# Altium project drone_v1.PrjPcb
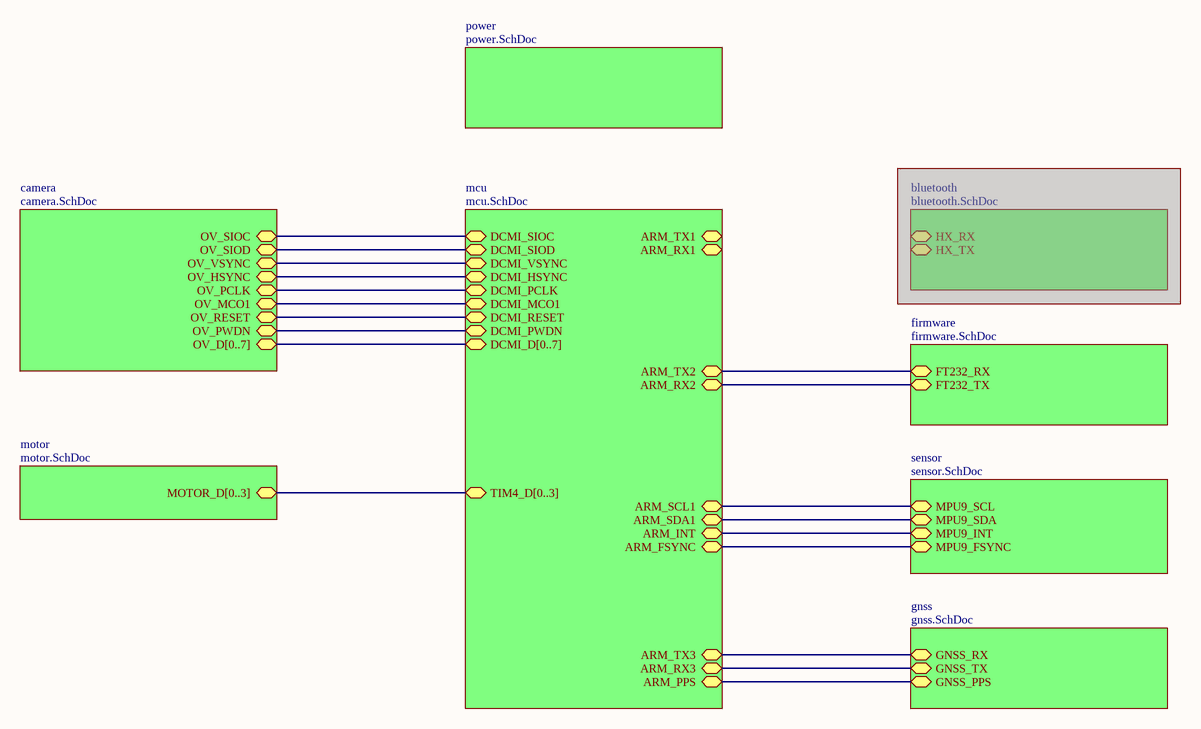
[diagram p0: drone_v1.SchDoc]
9 sheets, 128 parts. Net scope: hierarchical (ports join the sheet entries above them; power ports are global).
Board file: drone_v1.PcbDoc
Sheets:
  drone_v1.SchDoc
    mcu = mcu.SchDoc
    firmware = firmware.SchDoc
    power = power.SchDoc
    sensor = sensor.SchDoc
    gnss = gnss.SchDoc
    camera = camera.SchDoc
    motor = motor.SchDoc

## Sheet drone_v1.SchDoc
size A4

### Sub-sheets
bluetooth = bluetooth.SchDoc (masked out): HX_RX (bidir), HX_TX (bidir)
camera = camera.SchDoc: OV_SIOC (bidir), OV_SIOD (bidir), OV_VSYNC (bidir), OV_HSYNC (bidir), OV_PCLK (bidir), OV_MCO1 (bidir), OV_RESET (bidir), OV_PWDN (bidir), OV_D[0..7] (bidir)
firmware = firmware.SchDoc: FT232_RX (bidir), FT232_TX (bidir)
gnss = gnss.SchDoc: GNSS_RX (bidir), GNSS_TX (bidir), GNSS_PPS (bidir)
mcu = mcu.SchDoc: ARM_TX1 (bidir), ARM_RX1 (bidir), ARM_TX2 (bidir), ARM_RX2 (bidir), ARM_SCL1 (bidir), ARM_SDA1 (bidir), ARM_TX3 (bidir), ARM_RX3 (bidir), DCMI_SIOC (bidir), DCMI_SIOD (bidir), DCMI_VSYNC (bidir), DCMI_HSYNC (bidir), DCMI_PCLK (bidir), DCMI_MCO1 (bidir), DCMI_RESET (bidir), DCMI_PWDN (bidir), DCMI_D[0..7] (bidir), ARM_PPS (bidir), ARM_INT (bidir), ARM_FSYNC (bidir), TIM4_D[0..3] (bidir)
motor = motor.SchDoc: MOTOR_D[0..3] (bidir)
power = power.SchDoc: no entries
sensor = sensor.SchDoc: MPU9_SCL (bidir), MPU9_SDA (bidir), MPU9_INT (bidir), MPU9_FSYNC (bidir)

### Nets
OV_HSYNC: sheet mcu/DCMI_HSYNC, sheet camera/OV_HSYNC
OV_MCO1: sheet mcu/DCMI_MCO1, sheet camera/OV_MCO1
OV_PCLK: sheet mcu/DCMI_PCLK, sheet camera/OV_PCLK
OV_PWDN: sheet mcu/DCMI_PWDN, sheet camera/OV_PWDN
OV_RESET: sheet mcu/DCMI_RESET, sheet camera/OV_RESET
OV_SIOC: sheet mcu/DCMI_SIOC, sheet camera/OV_SIOC
OV_SIOD: sheet mcu/DCMI_SIOD, sheet camera/OV_SIOD
OV_VSYNC: sheet mcu/DCMI_VSYNC, sheet camera/OV_VSYNC
NetR42_2: sheet mcu/ARM_SCL1, sheet sensor/MPU9_SCL
NetR43_2: sheet mcu/ARM_SDA1, sheet sensor/MPU9_SDA
NetR52_1: sheet mcu/ARM_PPS, sheet gnss/GNSS_PPS
NetU1_25: sheet mcu/ARM_TX2, sheet firmware/FT232_RX
NetU1_26: sheet mcu/ARM_RX2, sheet firmware/FT232_TX
NetU1_51: sheet mcu/ARM_FSYNC, sheet sensor/MPU9_FSYNC
NetU1_52: sheet mcu/ARM_INT, sheet sensor/MPU9_INT
NetU1_55: sheet mcu/ARM_TX3, sheet gnss/GNSS_RX
NetU1_56: sheet mcu/ARM_RX3, sheet gnss/GNSS_TX

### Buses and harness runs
bus sheet camera/OV_D[0..7] = sheet mcu/DCMI_D[0..7]
bus sheet mcu/TIM4_D[0..3] = sheet motor/MOTOR_D[0..3]

## Sheet mcu.SchDoc
size A3
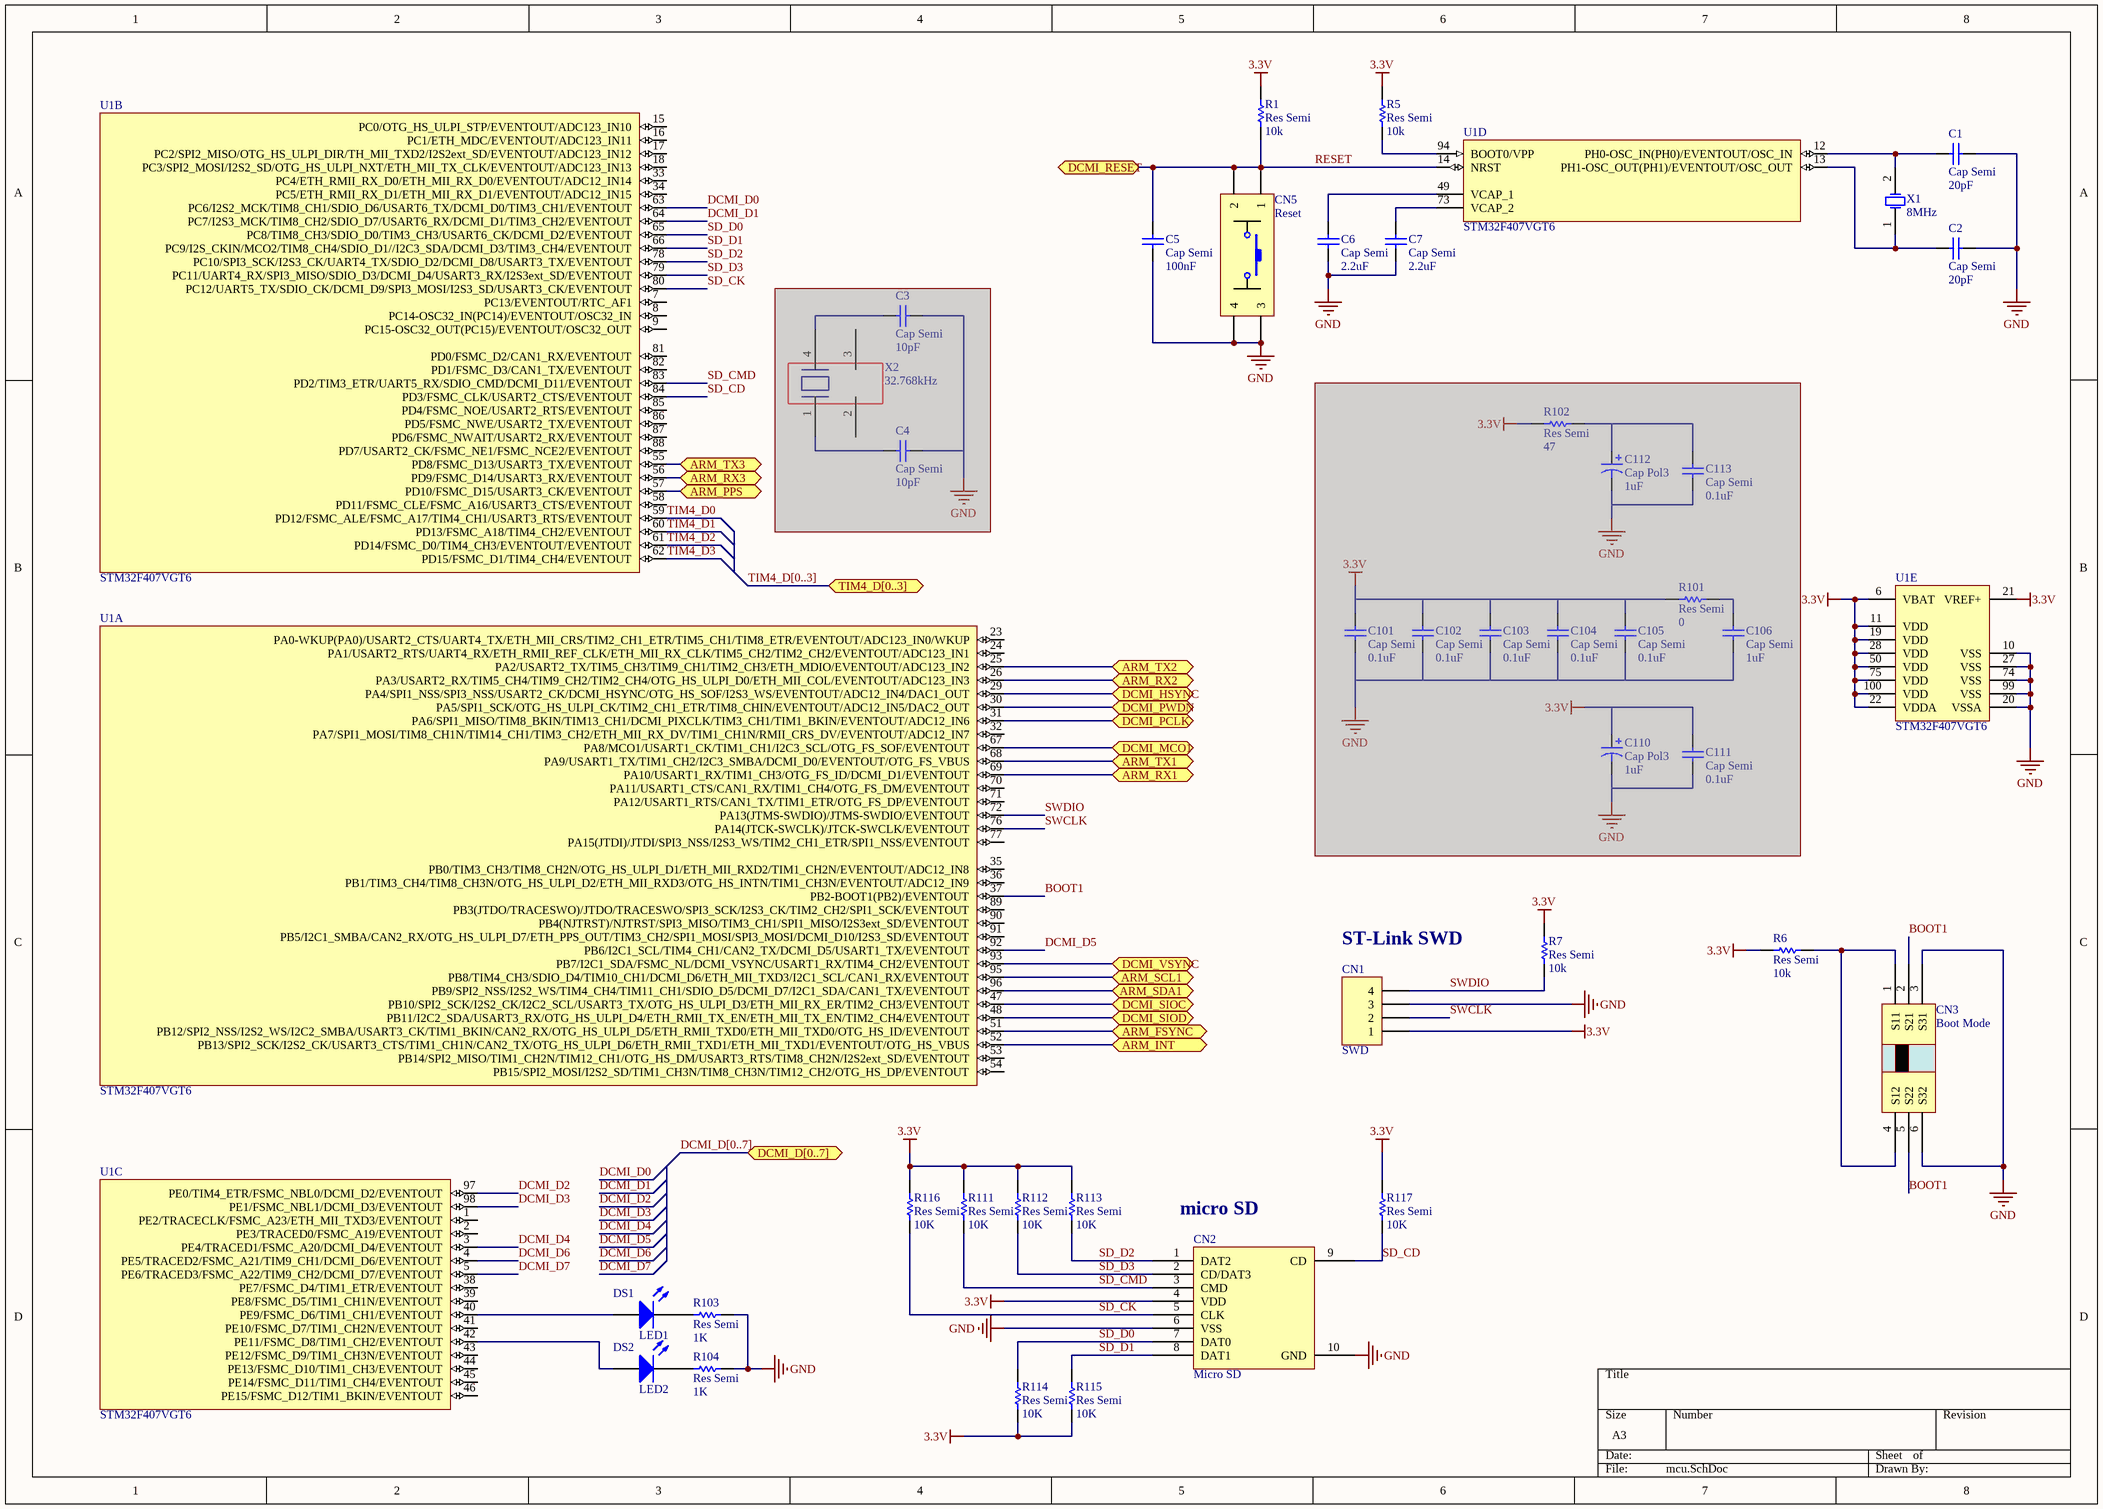
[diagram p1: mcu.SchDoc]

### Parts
C1  Cap Semi  value 20pF  [C1608-0603]
C2  Cap Semi  value 20pF  [C1608-0603]
C3  Cap Semi  value 10pF  [C1608-0603]  (masked out: inside a compile mask, not in the netlist)
C4  Cap Semi  value 10pF  [C1608-0603]  (masked out: inside a compile mask, not in the netlist)
C5  Cap Semi  value 100nF  [C1608-0603]
C6  Cap Semi  value 2.2uF  [C1608-0603]
C7  Cap Semi  value 2.2uF  [C1608-0603]
C101  Cap Semi  value 0.1uF  [C1608-0603]  (masked out: inside a compile mask, not in the netlist)
C102  Cap Semi  value 0.1uF  [C1608-0603]  (masked out: inside a compile mask, not in the netlist)
C103  Cap Semi  value 0.1uF  [C1608-0603]  (masked out: inside a compile mask, not in the netlist)
C104  Cap Semi  value 0.1uF  [C1608-0603]  (masked out: inside a compile mask, not in the netlist)
C105  Cap Semi  value 0.1uF  [C1608-0603]  (masked out: inside a compile mask, not in the netlist)
C106  Cap Semi  value 1uF  [C1608-0603]  (masked out: inside a compile mask, not in the netlist)
C110  Cap Pol3  value 1uF  [CC3216-1206]  (masked out: inside a compile mask, not in the netlist)
C111  Cap Semi  value 0.1uF  [C1608-0603]  (masked out: inside a compile mask, not in the netlist)
C112  Cap Pol3  value 1uF  [CC3216-1206]  (masked out: inside a compile mask, not in the netlist)
C113  Cap Semi  value 0.1uF  [C1608-0603]  (masked out: inside a compile mask, not in the netlist)
CN1  SWD  [HDR1X4H]
CN2  Micro SD  [MICRO_SD_PUSH]
CN3  Boot Mode  [SWITCH_6]
CN5  Reset  [Switch6X6]
DS1  LED1  [LED0603_AB]
DS2  LED2  [LED0603_AB]
R1  Res Semi  value 10k  [R1608-0603]
R5  Res Semi  value 10k  [R1608-0603]
R6  Res Semi  value 10k  [R1608-0603]
R7  Res Semi  value 10k  [R1608-0603]
R101  Res Semi  value 0  [R1608-0603]  (masked out: inside a compile mask, not in the netlist)
R102  Res Semi  value 47  [R1608-0603]  (masked out: inside a compile mask, not in the netlist)
R103  Res Semi  value 1K  [R1608-0603]
R104  Res Semi  value 1K  [R1608-0603]
R111  Res Semi  value 10K  [R1608-0603]
R112  Res Semi  value 10K  [R1608-0603]
R113  Res Semi  value 10K  [R1608-0603]
R114  Res Semi  value 10K  [R1608-0603]
R115  Res Semi  value 10K  [R1608-0603]
R116  Res Semi  value 10K  [R1608-0603]
R117  Res Semi  value 10K  [R1608-0603]
U1  STM32F407VGT6  [LQFP100_V]  (parts A,B,C,D,E of 5)
X1  8MHz  [XTAL-0.2]
X2  32.768kHz  [OSC_MC306]  (masked out: inside a compile mask, not in the netlist)

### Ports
ARM_FSYNC (bidir), ARM_INT (bidir), ARM_PPS (bidir), ARM_RX1 (bidir), ARM_RX2 (bidir), ARM_RX3 (bidir), ARM_SCL1 (bidir), ARM_SDA1 (bidir), ARM_TX1 (bidir), ARM_TX2 (bidir), ARM_TX3 (bidir), DCMI_D[0..7] (bidir), DCMI_HSYNC (bidir), DCMI_MCO1 (bidir), DCMI_PCLK (bidir), DCMI_PWDN (bidir), DCMI_RESET (bidir), DCMI_SIOC (bidir), DCMI_SIOD (bidir), DCMI_VSYNC (bidir), TIM4_D[0..3] (bidir)

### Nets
3.3V: CN1.1 CN2.4(VDD) R1.1 R5.1 R6.1 R7.1 R111.1 R112.1 R113.1 R114.2 R115.2 R116.1 R117.1 U1.6(VBAT) U1.11(VDD) U1.19(VDD) U1.21(VREF+) U1.22(VDDA) U1.28(VDD) U1.50(VDD) U1.75(VDD) U1.100(VDD)
GND: C1.1 C2.1 C5.2 C6.1 C7.1 CN1.3 CN2.6(VSS) CN2.10(GND) CN3.3(S31) CN3.6(S32) CN5.3 CN5.4 R103.2 R104.2 U1.10(VSS) U1.20(VSSA) U1.27(VSS) U1.74(VSS) U1.99(VSS)
BOOT1: CN3.2(S21) CN3.5(S22) U1.37(PB2-BOOT1(PB2)/EVENTOUT)
DCMI_D0: U1.63(PC6/I2S2_MCK/TIM8_CH1/SDIO_D6/USART6_TX/DCMI_D0/TIM3_CH1/EVENTOUT)
DCMI_D1: U1.64(PC7/I2S3_MCK/TIM8_CH2/SDIO_D7/USART6_RX/DCMI_D1/TIM3_CH2/EVENTOUT)
DCMI_D2: U1.97(PE0/TIM4_ETR/FSMC_NBL0/DCMI_D2/EVENTOUT)
DCMI_D3: U1.98(PE1/FSMC_NBL1/DCMI_D3/EVENTOUT)
DCMI_D4: U1.3(PE4/TRACED1/FSMC_A20/DCMI_D4/EVENTOUT)
DCMI_D5: U1.92(PB6/I2C1_SCL/TIM4_CH1/CAN2_TX/DCMI_D5/USART1_TX/EVENTOUT)
DCMI_D6: U1.4(PE5/TRACED2/FSMC_A21/TIM9_CH1/DCMI_D6/EVENTOUT)
DCMI_D7: U1.5(PE6/TRACED3/FSMC_A22/TIM9_CH2/DCMI_D7/EVENTOUT)
OV_HSYNC: U1.29(PA4/SPI1_NSS/SPI3_NSS/USART2_CK/DCMI_HSYNC/OTG_HS_SOF/I2S3_WS/EVENTOUT/ADC12_IN4/DAC1_OUT) ; port DCMI_HSYNC
OV_MCO1: U1.67(PA8/MCO1/USART1_CK/TIM1_CH1/I2C3_SCL/OTG_FS_SOF/EVENTOUT) ; port DCMI_MCO1
OV_PCLK: U1.31(PA6/SPI1_MISO/TIM8_BKIN/TIM13_CH1/DCMI_PIXCLK/TIM3_CH1/TIM1_BKIN/EVENTOUT/ADC12_IN6) ; port DCMI_PCLK
OV_PWDN: U1.30(PA5/SPI1_SCK/OTG_HS_ULPI_CK/TIM2_CH1_ETR/TIM8_CHIN/EVENTOUT/ADC12_IN5/DAC2_OUT) ; port DCMI_PWDN
OV_SIOC: U1.47(PB10/SPI2_SCK/I2S2_CK/I2C2_SCL/USART3_TX/OTG_HS_ULPI_D3/ETH_MII_RX_ER/TIM2_CH3/EVENTOUT) ; port DCMI_SIOC
OV_SIOD: U1.48(PB11/I2C2_SDA/USART3_RX/OTG_HS_ULPI_D4/ETH_RMII_TX_EN/ETH_MII_TX_EN/TIM2_CH4/EVENTOUT) ; port DCMI_SIOD
OV_VSYNC: U1.93(PB7/I2C1_SDA/FSMC_NL/DCMI_VSYNC/USART1_RX/TIM4_CH2/EVENTOUT) ; port DCMI_VSYNC
RESET: C5.1 CN5.1 CN5.2 R1.2 U1.14(NRST) ; port DCMI_RESET  [project net OV_RESET]
SD_CD: CN2.9(CD) R117.2 U1.84(PD3/FSMC_CLK/USART2_CTS/EVENTOUT)
SD_CK: CN2.5(CLK) R116.2 U1.80(PC12/UART5_TX/SDIO_CK/DCMI_D9/SPI3_MOSI/I2S3_SD/USART3_CK/EVENTOUT)
SD_CMD: CN2.3(CMD) R111.2 U1.83(PD2/TIM3_ETR/UART5_RX/SDIO_CMD/DCMI_D11/EVENTOUT)
SD_D0: CN2.7(DAT0) R114.1 U1.65(PC8/TIM8_CH3/SDIO_D0/TIM3_CH3/USART6_CK/DCMI_D2/EVENTOUT)
SD_D1: CN2.8(DAT1) R115.1 U1.66(PC9/I2S_CKIN/MCO2/TIM8_CH4/SDIO_D1//I2C3_SDA/DCMI_D3/TIM3_CH4/EVENTOUT)
SD_D2: CN2.1(DAT2) R113.2 U1.78(PC10/SPI3_SCK/I2S3_CK/UART4_TX/SDIO_D2/DCMI_D8/USART3_TX/EVENTOUT)
SD_D3: CN2.2(CD/DAT3) R112.2 U1.79(PC11/UART4_RX/SPI3_MISO/SDIO_D3/DCMI_D4/USART3_RX/I2S3ext_SD/EVENTOUT)
SWCLK: CN1.2 U1.76(PA14(JTCK-SWCLK)/JTCK-SWCLK/EVENTOUT)
SWDIO: CN1.4 R7.2 U1.72(PA13(JTMS-SWDIO)/JTMS-SWDIO/EVENTOUT)
TIM4_D0: U1.59(PD12/FSMC_ALE/FSMC_A17/TIM4_CH1/USART3_RTS/EVENTOUT)  [project net MOTOR_D0]
TIM4_D1: U1.60(PD13/FSMC_A18/TIM4_CH2/EVENTOUT)  [project net MOTOR_D1]
TIM4_D2: U1.61(PD14/FSMC_D0/TIM4_CH3/EVENTOUT/EVENTOUT)  [project net MOTOR_D2]
TIM4_D3: U1.62(PD15/FSMC_D1/TIM4_CH4/EVENTOUT)  [project net MOTOR_D3]
NetC1_2: C1.2 U1.12(PH0-OSC_IN(PH0)/EVENTOUT/OSC_IN) X1.2(OSC2)
NetC2_2: C2.2 U1.13(PH1-OSC_OUT(PH1)/EVENTOUT/OSC_OUT) X1.1(OSC1)
NetC6_2: C6.2 U1.49(VCAP_1)
NetC7_2: C7.2 U1.73(VCAP_2)
NetCN3_1: CN3.1(S11) CN3.4(S12) R6.2
NetDS1_1: DS1.1(A) U1.40(PE9/FSMC_D6/TIM1_CH1/EVENTOUT)
NetDS1_2: DS1.2(K) R103.1
NetDS2_1: DS2.1(A) U1.42(PE11/FSMC_D8/TIM1_CH2/EVENTOUT)
NetDS2_2: DS2.2(K) R104.1
NetR5_2: R5.2 U1.94(BOOT0/VPP)
NetR42_2: U1.95(PB8/TIM4_CH3/SDIO_D4/TIM10_CH1/DCMI_D6/ETH_MII_TXD3/I2C1_SCL/CAN1_RX/EVENTOUT) ; port ARM_SCL1
NetR43_2: U1.96(PB9/SPI2_NSS/I2S2_WS/TIM4_CH4/TIM11_CH1/SDIO_D5/DCMI_D7/I2C1_SDA/CAN1_TX/EVENTOUT) ; port ARM_SDA1
NetR52_1: U1.57(PD10/FSMC_D15/USART3_CK/EVENTOUT) ; port ARM_PPS
NetU1_25: U1.25(PA2/USART2_TX/TIM5_CH3/TIM9_CH1/TIM2_CH3/ETH_MDIO/EVENTOUT/ADC123_IN2) ; port ARM_TX2
NetU1_26: U1.26(PA3/USART2_RX/TIM5_CH4/TIM9_CH2/TIM2_CH4/OTG_HS_ULPI_D0/ETH_MII_COL/EVENTOUT/ADC123_IN3) ; port ARM_RX2
NetU1_51: U1.51(PB12/SPI2_NSS/I2S2_WS/I2C2_SMBA/USART3_CK/TIM1_BKIN/CAN2_RX/OTG_HS_ULPI_D5/ETH_RMII_TXD0/ETH_MII_TXD0/OTG_HS_ID/EVENTOUT) ; port ARM_FSYNC
NetU1_52: U1.52(PB13/SPI2_SCK/I2S2_CK/USART3_CTS/TIM1_CH1N/CAN2_TX/OTG_HS_ULPI_D6/ETH_RMII_TXD1/ETH_MII_TXD1/EVENTOUT/OTG_HS_VBUS) ; port ARM_INT
NetU1_55: U1.55(PD8/FSMC_D13/USART3_TX/EVENTOUT) ; port ARM_TX3
NetU1_56: U1.56(PD9/FSMC_D14/USART3_RX/EVENTOUT) ; port ARM_RX3
NetU1_68: U1.68(PA9/USART1_TX/TIM1_CH2/I2C3_SMBA/DCMI_D0/EVENTOUT/OTG_FS_VBUS) ; port ARM_TX1
NetU1_69: U1.69(PA10/USART1_RX/TIM1_CH3/OTG_FS_ID/DCMI_D1/EVENTOUT) ; port ARM_RX1

Not connected (* = marked no-connect by the designer): U1 1(PE2/TRACECLK/FSMC_A23/ETH_MII_TXD3/EVENTOUT) 2(PE3/TRACED0/FSMC_A19/EVENTOUT) 7(PC13/EVENTOUT/RTC_AF1) 8(PC14-OSC32_IN(PC14)/EVENTOUT/OSC32_IN) 9(PC15-OSC32_OUT(PC15)/EVENTOUT/OSC32_OUT) 15(PC0/OTG_HS_ULPI_STP/EVENTOUT/ADC123_IN10) 16(PC1/ETH_MDC/EVENTOUT/ADC123_IN11) 17(PC2/SPI2_MISO/OTG_HS_ULPI_DIR/TH_MII_TXD2/I2S2ext_SD/EVENTOUT/ADC123_IN12) 18(PC3/SPI2_MOSI/I2S2_SD/OTG_HS_ULPI_NXT/ETH_MII_TX_CLK/EVENTOUT/ADC123_IN13) 23(PA0-WKUP(PA0)/USART2_CTS/UART4_TX/ETH_MII_CRS/TIM2_CH1_ETR/TIM5_CH1/TIM8_ETR/EVENTOUT/ADC123_IN0/WKUP) 24(PA1/USART2_RTS/UART4_RX/ETH_RMII_REF_CLK/ETH_MII_RX_CLK/TIM5_CH2/TIM2_CH2/EVENTOUT/ADC123_IN1) 32(PA7/SPI1_MOSI/TIM8_CH1N/TIM14_CH1/TIM3_CH2/ETH_MII_RX_DV/TIM1_CH1N/RMII_CRS_DV/EVENTOUT/ADC12_IN7) 33(PC4/ETH_RMII_RX_D0/ETH_MII_RX_D0/EVENTOUT/ADC12_IN14) 34(PC5/ETH_RMII_RX_D1/ETH_MII_RX_D1/EVENTOUT/ADC12_IN15) 35(PB0/TIM3_CH3/TIM8_CH2N/OTG_HS_ULPI_D1/ETH_MII_RXD2/TIM1_CH2N/EVENTOUT/ADC12_IN8) 36(PB1/TIM3_CH4/TIM8_CH3N/OTG_HS_ULPI_D2/ETH_MII_RXD3/OTG_HS_INTN/TIM1_CH3N/EVENTOUT/ADC12_IN9) 38(PE7/FSMC_D4/TIM1_ETR/EVENTOUT) 39(PE8/FSMC_D5/TIM1_CH1N/EVENTOUT) 41(PE10/FSMC_D7/TIM1_CH2N/EVENTOUT) 43(PE12/FSMC_D9/TIM1_CH3N/EVENTOUT) 44(PE13/FSMC_D10/TIM1_CH3/EVENTOUT) 45(PE14/FSMC_D11/TIM1_CH4/EVENTOUT) 46(PE15/FSMC_D12/TIM1_BKIN/EVENTOUT) 53(PB14/SPI2_MISO/TIM1_CH2N/TIM12_CH1/OTG_HS_DM/USART3_RTS/TIM8_CH2N/I2S2ext_SD/EVENTOUT) 54(PB15/SPI2_MOSI/I2S2_SD/TIM1_CH3N/TIM8_CH3N/TIM12_CH2/OTG_HS_DP/EVENTOUT) 58(PD11/FSMC_CLE/FSMC_A16/USART3_CTS/EVENTOUT) 70(PA11/USART1_CTS/CAN1_RX/TIM1_CH4/OTG_FS_DM/EVENTOUT) 71(PA12/USART1_RTS/CAN1_TX/TIM1_ETR/OTG_FS_DP/EVENTOUT) 77(PA15(JTDI)/JTDI/SPI3_NSS/I2S3_WS/TIM2_CH1_ETR/SPI1_NSS/EVENTOUT) 81(PD0/FSMC_D2/CAN1_RX/EVENTOUT) 82(PD1/FSMC_D3/CAN1_TX/EVENTOUT) 85(PD4/FSMC_NOE/USART2_RTS/EVENTOUT) 86(PD5/FSMC_NWE/USART2_TX/EVENTOUT) 87(PD6/FSMC_NWAIT/USART2_RX/EVENTOUT) 88(PD7/USART2_CK/FSMC_NE1/FSMC_NCE2/EVENTOUT) 89(PB3(JTDO/TRACESWO)/JTDO/TRACESWO/SPI3_SCK/I2S3_CK/TIM2_CH2/SPI1_SCK/EVENTOUT) 90(PB4(NJTRST)/NJTRST/SPI3_MISO/TIM3_CH1/SPI1_MISO/I2S3ext_SD/EVENTOUT) 91(PB5/I2C1_SMBA/CAN2_RX/OTG_HS_ULPI_D7/ETH_PPS_OUT/TIM3_CH2/SPI1_MOSI/SPI3_MOSI/DCMI_D10/I2S3_SD/EVENTOUT)

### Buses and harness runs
bus DCMI_D[0..7] = port DCMI_D[0..7]
bus TIM4_D[0..3] = port TIM4_D[0..3]

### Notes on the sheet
- (near CN1) ST-Link SWD
- (near CN2) micro SD

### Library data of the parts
C1-C7 C101-C106 C111 C113 = Cap Semi: Capacitor (Semiconductor SIM Model)
C110 C112 = Cap Pol3: Polarized Capacitor (Surface Mount)
CN1 = Header 4H: Header, 4-Pin, Right Angle
CN2 = MICRO_SD_PUSH
CN3 = SWITCH_6
CN5 = Switch6X6: Switch
DS1 DS2 = LED3: Typical BLUE SiC LED
R1 R5-R7 R101-R104 R111-R117 = Res Semi: Semiconductor Resistor
X1 = XTAL: Crystal Oscillator
X2 = OSC_MC306

## Sheet firmware.SchDoc
size A4
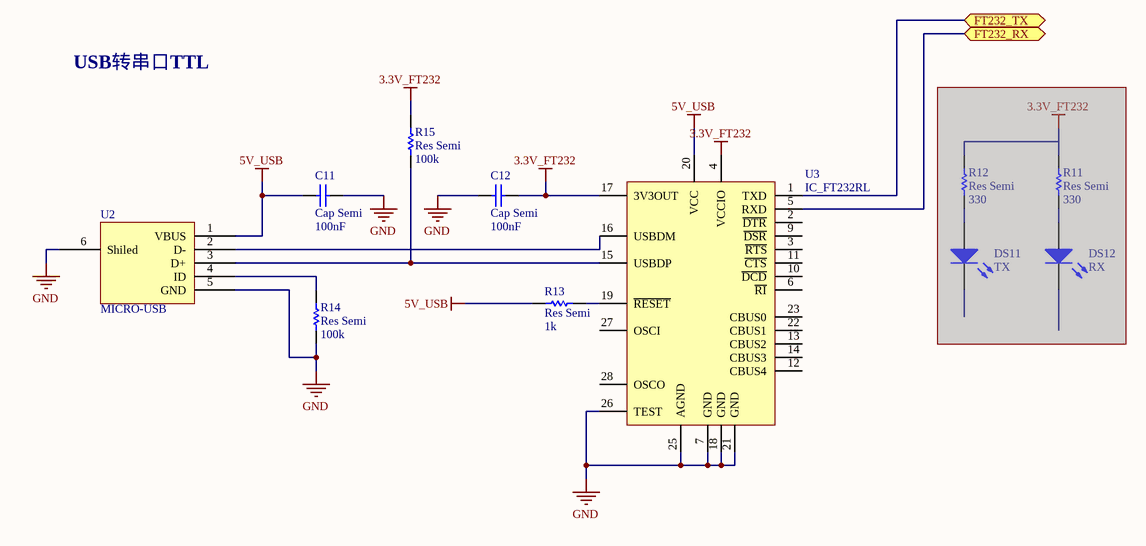
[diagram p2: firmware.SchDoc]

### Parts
C11  Cap Semi  value 100nF  [C1608-0603]
C12  Cap Semi  value 100nF  [C1608-0603]
DS11  TX  [LED0603_AB]  (masked out: inside a compile mask, not in the netlist)
DS12  RX  [LED0603_AB]  (masked out: inside a compile mask, not in the netlist)
R11  Res Semi  value 330  [R1608-0603]  (masked out: inside a compile mask, not in the netlist)
R12  Res Semi  value 330  [R1608-0603]  (masked out: inside a compile mask, not in the netlist)
R13  Res Semi  value 1k  [R1608-0603]
R14  Res Semi  value 100k  [R1608-0603]
R15  Res Semi  value 100k  [R1608-0603]
U2  MICRO-USB  [MICRO-USB]
U3  IC_FT232RL  [SSOP-28]

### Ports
FT232_RX (bidir), FT232_TX (bidir)

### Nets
3.3V_FT232: C12.2 R15.1 U3.4(VCCIO) U3.17(3V3OUT)
5V_USB: C11.1 R13.1 U2.1(VBUS) U3.20(VCC)
GND: C11.2 C12.1 R14.2 U2.5(GND) U2.6(Shiled) U3.7(GND) U3.18(GND) U3.21(GND) U3.25(AGND) U3.26(TEST)
NetR13_2: R13.2 U3.19(~{RESET})
NetR14_1: R14.1 U2.4(ID)
NetR15_2: R15.2 U2.3(D+) U3.15(USBDP)
NetU1_25: U3.5(RXD) ; port FT232_RX
NetU1_26: U3.1(TXD) ; port FT232_TX
NetU2_2: U2.2(D-) U3.16(USBDM)

Not connected (* = marked no-connect by the designer): U3 2(~{DTR}) 3(~{RTS}) 6(~{RI}) 8(NC) 9(~{DSR}) 10(~{DCD}) 11(~{CTS}) 12(CBUS4) 13(CBUS2) 14(CBUS3) 22(CBUS1) 23(CBUS0) 24(NC) 27(OSCI) 28(OSCO)

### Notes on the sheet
- USB转串口TTL

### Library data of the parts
C11 C12 = Cap Semi: Capacitor (Semiconductor SIM Model)
DS11 DS12 = LED3: Typical BLUE SiC LED
R11-R15 = Res Semi: Semiconductor Resistor
U3 = IC_FT232RL: FT232R USB UART

## Sheet power.SchDoc
size A4
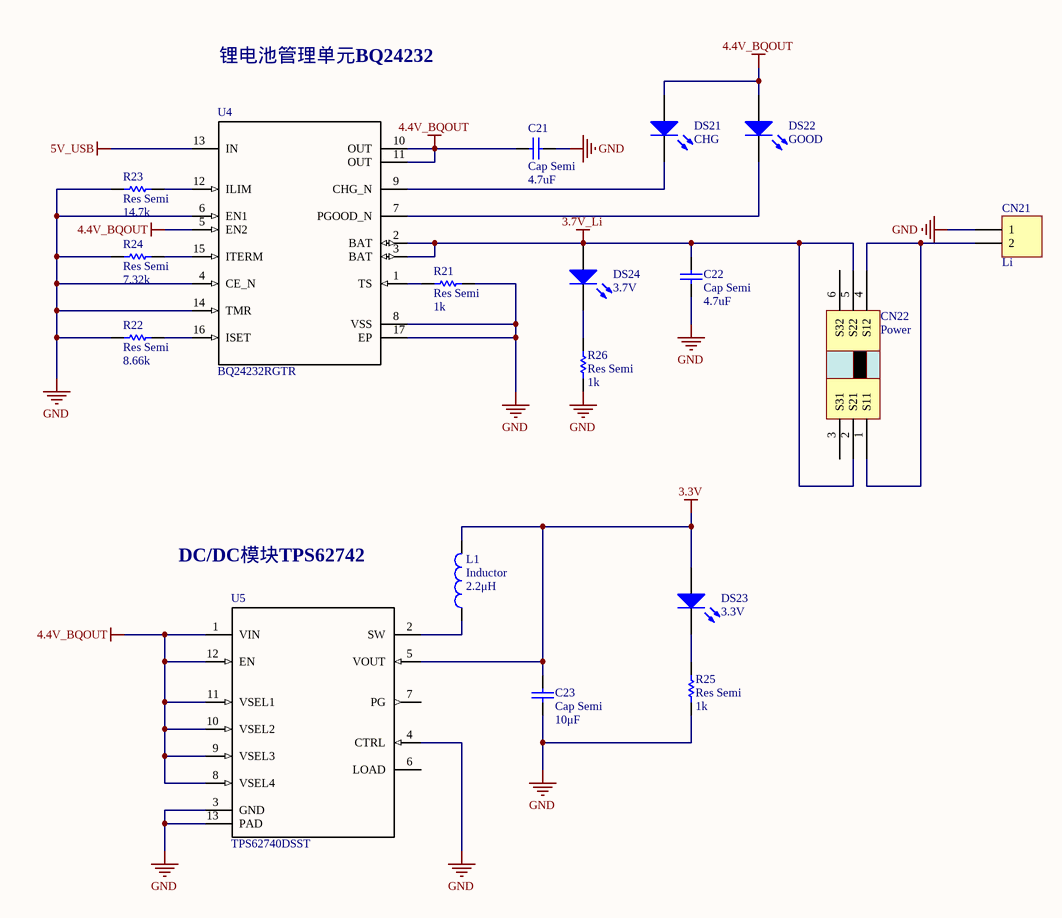
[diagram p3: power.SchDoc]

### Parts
C21  Cap Semi  value 4.7uF  [C1608-0603]
C22  Cap Semi  value 4.7uF  [C1608-0603]
C23  Cap Semi  value 10μF  [C1608-0603]
CN21  Li  [HDR1X2]
CN22  Power  [SWITCH_6]
DS21  CHG  [LED0603_AB]
DS22  GOOD  [LED0603_AB]
DS23  3.3V  [LED0603_AB]
DS24  3.7V  [LED0603_AB]
L1  Inductor  value 2.2μH  [I1608-0603]
R21  Res Semi  value 1k  [R1608-0603]
R22  Res Semi  value 8.66k  [R1608-0603]
R23  Res Semi  value 14.7k  [R1608-0603]
R24  Res Semi  value 7.32k  [R1608-0603]
R25  Res Semi  value 1k  [R1608-0603]
R26  Res Semi  value 1k  [R1608-0603]
U4  BQ24232RGTR  [RGT0016C]
U5  TPS62740DSST  [DSS0012A]

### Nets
3.3V: C23.1 DS23.1(A) L1.2 U5.5(VOUT)
3.7V_Li: C22.2 CN22.2(S21) CN22.5(S22) DS24.1(A) U4.2(BAT) U4.3(BAT)
4.4V_BQOUT: C21.2 DS21.1(A) DS22.1(A) U4.5(EN2) U4.10(OUT) U4.11(OUT) U5.1(VIN) U5.8(VSEL4) U5.9(VSEL3) U5.10(VSEL2) U5.11(VSEL1) U5.12(EN)
5V_USB: U4.13(IN)
GND: C21.1 C22.1 C23.2 CN21.1 R21.2 R22.1 R23.1 R24.1 R25.1 R26.1 U4.4(CE_N) U4.6(EN1) U4.8(VSS) U4.14(TMR) U4.17(EP) U5.3(GND) U5.4(CTRL) U5.13(PAD)
NetCN21_2: CN21.2 CN22.1(S11) CN22.4(S12)
NetDS21_2: DS21.2(K) U4.9(CHG_N)
NetDS22_2: DS22.2(K) U4.7(PGOOD_N)
NetDS23_2: DS23.2(K) R25.2
NetDS24_2: DS24.2(K) R26.2
NetL1_1: L1.1 U5.2(SW)
NetR21_1: R21.1 U4.1(TS)
NetR22_2: R22.2 U4.16(ISET)
NetR23_2: R23.2 U4.12(ILIM)
NetR24_2: R24.2 U4.15(ITERM)

Not connected (* = marked no-connect by the designer): CN22 3(S31) 6(S32); U5 6(LOAD) 7(PG)

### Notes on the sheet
- 锂电池管理单元BQ24232
- DC/DC模块TPS62742

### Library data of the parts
C21-C23 = Cap Semi: Capacitor (Semiconductor SIM Model)
CN21 = Header 2: Header, 2-Pin
CN22 = SWITCH_6
DS21-DS24 = LED3: Typical BLUE SiC LED
L1 = Inductor: Code_IEC: 1005
R21-R26 = Res Semi: Semiconductor Resistor
U4 = BQ24232RGTR: Imported; Alternate PartNumber: BQ24232RGTT; Manufacturer: Texas Instruments; CompType: IC; PIN_COUNT: 17
U5 = TPS62740DSST: Imported; Alternate Manufacturer: None; Manufacturer: Texas Instruments; CurrentTime: Not shown in title block; DocumentNumber: 1; SymbolCreator: a0411947; CompType: IC; U/M: EA; Designator: U?; PIN_COUNT: 13

## Sheet sensor.SchDoc
size A4
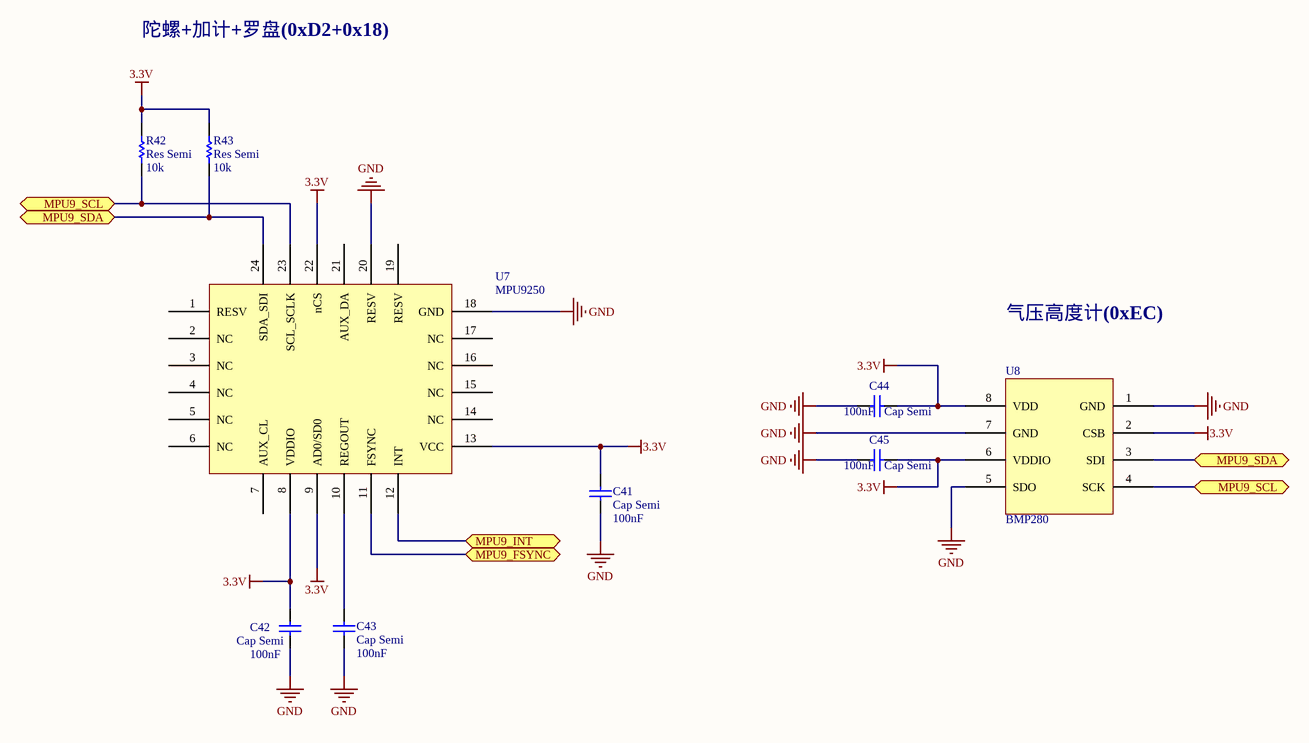
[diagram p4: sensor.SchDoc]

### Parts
C41  Cap Semi  value 100nF  [C1608-0603]
C42  Cap Semi  value 100nF  [C1608-0603]
C43  Cap Semi  value 100nF  [C1608-0603]
C44  Cap Semi  value 100nF  [C1608-0603]
C45  Cap Semi  value 100nF  [C1608-0603]
R42  Res Semi  value 10k  [R1608-0603]
R43  Res Semi  value 10k  [R1608-0603]
U7  MPU9250  [QFN24_3X3_MPU9250]
U8  BMP280  [LGA8_BMP280]

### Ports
MPU9_FSYNC (bidir), MPU9_INT (bidir), MPU9_SCL (bidir), MPU9_SDA (bidir)

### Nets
3.3V: C41.1 C42.1 C44.2 C45.2 R42.1 R43.1 U7.8(VDDIO) U7.9(AD0/SD0) U7.13(VCC) U7.22(nCS) U8.2(CSB) U8.6(VDDIO) U8.8(VDD)
GND: C41.2 C42.2 C43.2 C44.1 C45.1 U7.18(GND) U7.20(RESV) U8.1(GND) U8.5(SDO) U8.7(GND)
NetC43_1: C43.1 U7.10(REGOUT)
NetR42_2: R42.2 U7.23(SCL_SCLK) U8.4(SCK) ; port MPU9_SCL
NetR43_2: R43.2 U7.24(SDA_SDI) U8.3(SDI) ; port MPU9_SDA
NetU1_51: U7.11(FSYNC) ; port MPU9_FSYNC
NetU1_52: U7.12(INT) ; port MPU9_INT

Not connected (* = marked no-connect by the designer): U7 1(RESV) 2(NC) 3(NC) 4(NC) 5(NC) 6(NC) 7(AUX_CL) 14(NC) 15(NC) 16(NC) 17(NC) 19(RESV) 21(AUX_DA)

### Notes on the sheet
- 陀螺+加计+罗盘(0xD2+0x18)
- 气压高度计(0xEC)

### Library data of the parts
C41-C45 = Cap Semi: Capacitor (Semiconductor SIM Model)
R42 R43 = Res Semi: Semiconductor Resistor
U7 = QFN24_3X3_MPU9250
U8 = LGA8_BMP280

## Sheet gnss.SchDoc
size A4
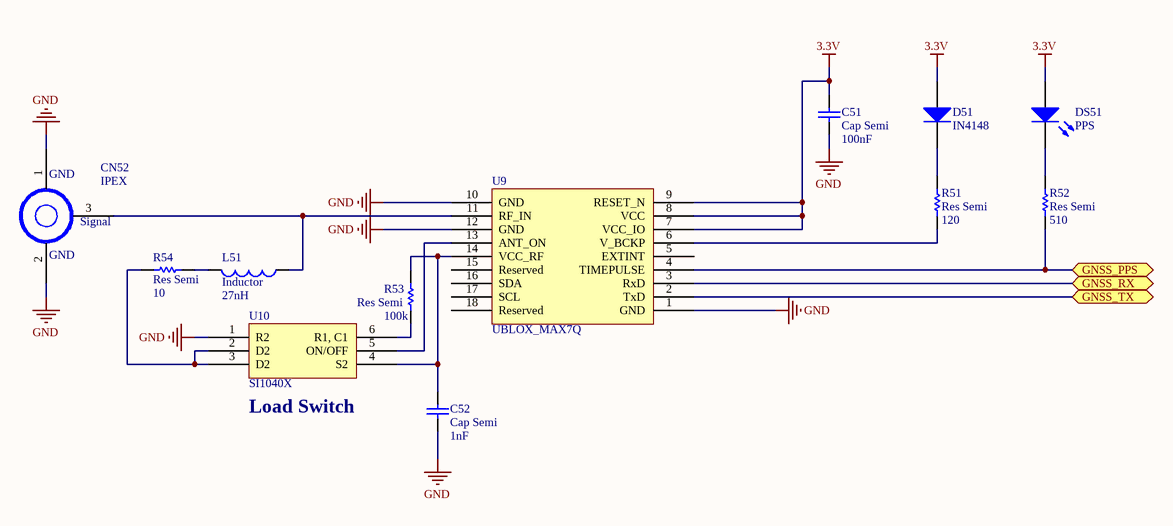
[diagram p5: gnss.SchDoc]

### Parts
C51  Cap Semi  value 100nF  [C1608-0603]
C52  Cap Semi  value 1nF  [C1608-0603]
CN52  IPEX  [IPEX]
D51  IN4148  [D1206]
DS51  PPS  [LED0603_AB]
L51  Inductor  value 27nH  [I1608-0603]
R51  Res Semi  value 120  [R1608-0603]
R52  Res Semi  value 510  [R1608-0603]
R53  Res Semi  value 100k  [R1608-0603]
R54  Res Semi  value 10  [R1608-0603]
U9  UBLOX_MAX7Q  [UBLOX_MAX7Q]
U10  SI1040X  [SI1040X]

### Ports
GNSS_PPS (bidir), GNSS_RX (bidir), GNSS_TX (bidir)

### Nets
3.3V: C51.1 D51.1(A) DS51.1(A) U9.7(VCC_IO) U9.8(VCC) U9.9(RESET_N)
GND: C51.2 C52.2 CN52.1(GND) CN52.2(GND) U9.1(GND) U9.10(GND) U9.12(GND) U10.1(R2)
NetC52_1: C52.1 R53.1 U9.14(VCC_RF) U10.4(S2)
NetCN52_3: CN52.3(Sig) L51.1 U9.11(RF_IN)
NetD51_2: D51.2(K) R51.2
NetDS51_2: DS51.2(K) R52.2
NetL51_2: L51.2 R54.2
NetR51_1: R51.1 U9.6(V_BCKP)
NetR52_1: R52.1 U9.4(TIMEPULSE) ; port GNSS_PPS
NetR53_2: R53.2 U10.6(R1,_C1)
NetR54_1: R54.1 U10.2(D2) U10.3(D2)
NetU1_55: U9.3(RxD) ; port GNSS_RX
NetU1_56: U9.2(TxD) ; port GNSS_TX
NetU9_13: U9.13(ANT_ON) U10.5(ON/OFF)

Not connected (* = marked no-connect by the designer): U9 5(EXTINT) 15(Reserved) 16(SDA) 17(SCL) 18(Reserved)

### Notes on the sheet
- (near U10) Load Switch

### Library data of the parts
C51 C52 = Cap Semi: Capacitor (Semiconductor SIM Model)
D51 = Diode: Default Diode
DS51 = LED3: Typical BLUE SiC LED
L51 = Inductor: Code_IEC: 1005
R51-R54 = Res Semi: Semiconductor Resistor

## Sheet camera.SchDoc
size A4
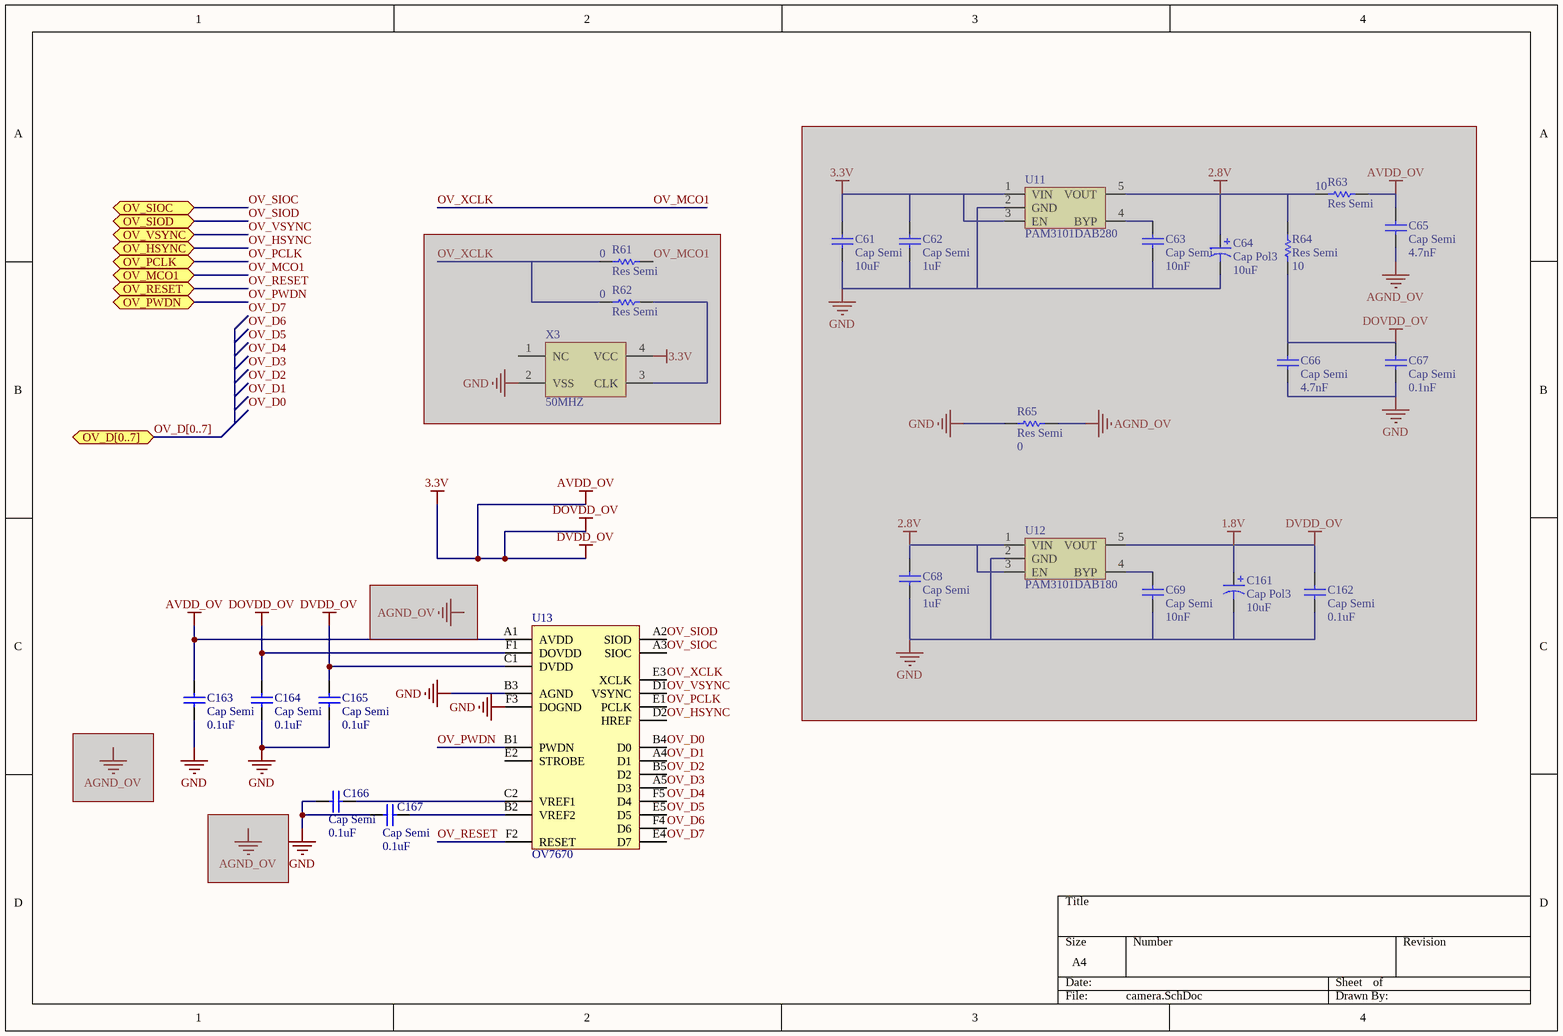
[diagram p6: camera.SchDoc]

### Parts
C61  Cap Semi  value 10uF  [C1608-0603]  (masked out: inside a compile mask, not in the netlist)
C62  Cap Semi  value 1uF  [C1608-0603]  (masked out: inside a compile mask, not in the netlist)
C63  Cap Semi  value 10nF  [C1608-0603]  (masked out: inside a compile mask, not in the netlist)
C64  Cap Pol3  value 10uF  [CC3216-1206]  (masked out: inside a compile mask, not in the netlist)
C65  Cap Semi  value 4.7nF  [C1608-0603]  (masked out: inside a compile mask, not in the netlist)
C66  Cap Semi  value 4.7nF  [C1608-0603]  (masked out: inside a compile mask, not in the netlist)
C67  Cap Semi  value 0.1nF  [C1608-0603]  (masked out: inside a compile mask, not in the netlist)
C68  Cap Semi  value 1uF  [C1608-0603]  (masked out: inside a compile mask, not in the netlist)
C69  Cap Semi  value 10nF  [C1608-0603]  (masked out: inside a compile mask, not in the netlist)
C161  Cap Pol3  value 10uF  [CC3216-1206]  (masked out: inside a compile mask, not in the netlist)
C162  Cap Semi  value 0.1uF  [C1608-0603]  (masked out: inside a compile mask, not in the netlist)
C163  Cap Semi  value 0.1uF  [C1608-0603]
C164  Cap Semi  value 0.1uF  [C1608-0603]
C165  Cap Semi  value 0.1uF  [C1608-0603]
C166  Cap Semi  value 0.1uF  [C1608-0603]
C167  Cap Semi  value 0.1uF  [C1608-0603]
R61  Res Semi  value 0  [R1608-0603]  (masked out: inside a compile mask, not in the netlist)
R62  Res Semi  value 0  [R1608-0603]  (masked out: inside a compile mask, not in the netlist)
R63  Res Semi  value 10  [R1608-0603]  (masked out: inside a compile mask, not in the netlist)
R64  Res Semi  value 10  [R1608-0603]  (masked out: inside a compile mask, not in the netlist)
R65  Res Semi  value 0  [R1608-0603]  (masked out: inside a compile mask, not in the netlist)
U11  PAM3101DAB280  [SOT-23-5]  (masked out: inside a compile mask, not in the netlist)
U12  PAM3101DAB180  [SOT-23-5]  (masked out: inside a compile mask, not in the netlist)
U13  OV7670  [OV7670-22]
X3  50MHZ  [OSC_50M]  (masked out: inside a compile mask, not in the netlist)

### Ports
OV_D[0..7] (bidir), OV_HSYNC (bidir), OV_MCO1 (bidir), OV_PCLK (bidir), OV_PWDN (bidir), OV_RESET (bidir), OV_SIOC (bidir), OV_SIOD (bidir), OV_VSYNC (bidir)

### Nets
3.3V: C163.1 C164.1 C165.1 U13.A1(AVDD) U13.C1(DVDD) U13.F1(DOVDD)  [also labelled AVDD_OV, DOVDD_OV, DVDD_OV]
GND: C163.2 C164.2 C165.2 C166.1 C167.1 U13.B3(AGND) U13.F3(DOGND)
OV_D0: U13.B4(D0)  [project net DCMI_D0]
OV_D1: U13.A4(D1)  [project net DCMI_D1]
OV_D2: U13.B5(D2)  [project net DCMI_D2]
OV_D3: U13.A5(D3)  [project net DCMI_D3]
OV_D4: U13.F5(D4)  [project net DCMI_D4]
OV_D5: U13.E5(D5)  [project net DCMI_D5]
OV_D6: U13.F4(D6)  [project net DCMI_D6]
OV_D7: U13.E4(D7)  [project net DCMI_D7]
OV_HSYNC: U13.D2(HREF) ; port OV_HSYNC
OV_MCO1: U13.E3(XCLK) ; port OV_MCO1  [also labelled OV_XCLK]
OV_PCLK: U13.E1(PCLK) ; port OV_PCLK
OV_PWDN: U13.B1(PWDN) ; port OV_PWDN
OV_RESET: U13.F2(RESET) ; port OV_RESET
OV_SIOC: U13.A3(SIOC) ; port OV_SIOC
OV_SIOD: U13.A2(SIOD) ; port OV_SIOD
OV_VSYNC: U13.D1(VSYNC) ; port OV_VSYNC
NetC166_2: C166.2 U13.C2(VREF1)
NetC167_2: C167.2 U13.B2(VREF2)

Not connected (* = marked no-connect by the designer): U13 E2(STROBE)

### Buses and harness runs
bus OV_D[0..7] = port OV_D[0..7]

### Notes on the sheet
- Labels drawn without touching a wire or pin: OV_D0, OV_D1, OV_D2, OV_D3, OV_D4, OV_D5, OV_D6, OV_D7

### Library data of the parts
C61-C63 C65-C69 C162-C167 = Cap Semi: Capacitor (Semiconductor SIM Model)
C64 C161 = Cap Pol3: Polarized Capacitor (Surface Mount)
R61-R65 = Res Semi: Semiconductor Resistor
U11 U12 = PAM3101DAB
X3 = OSCIL

## Sheet motor.SchDoc
size A4
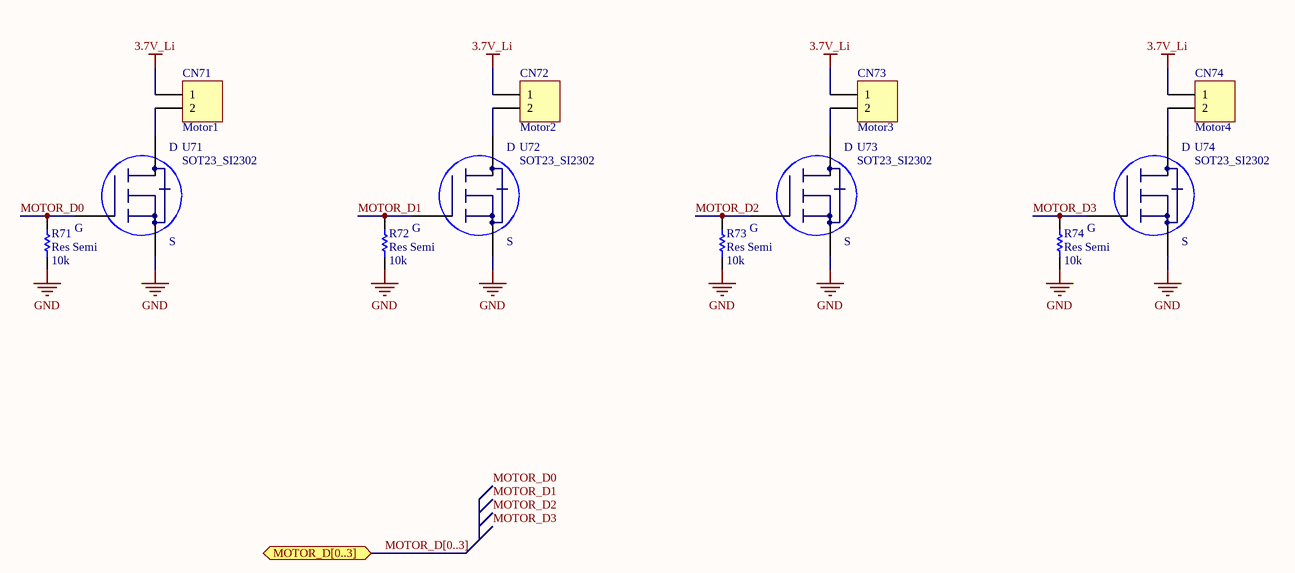
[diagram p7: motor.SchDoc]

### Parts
CN71  Motor1  [HDR1X2]
CN72  Motor2  [HDR1X2]
CN73  Motor3  [HDR1X2]
CN74  Motor4  [HDR1X2]
R71  Res Semi  value 10k  [R1608-0603]
R72  Res Semi  value 10k  [R1608-0603]
R73  Res Semi  value 10k  [R1608-0603]
R74  Res Semi  value 10k  [R1608-0603]
U71  SOT23_SI2302  [SOT23_SI2302]
U72  SOT23_SI2302  [SOT23_SI2302]
U73  SOT23_SI2302  [SOT23_SI2302]
U74  SOT23_SI2302  [SOT23_SI2302]

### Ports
MOTOR_D[0..3] (bidir)

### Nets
3.7V_Li: CN71.1 CN72.1 CN73.1 CN74.1
GND: R71.1 R72.1 R73.1 R74.1 U71.2(S) U72.2(S) U73.2(S) U74.2(S)
MOTOR_D0: R71.2 U71.1(G)
MOTOR_D1: R72.2 U72.1(G)
MOTOR_D2: R73.2 U73.1(G)
MOTOR_D3: R74.2 U74.1(G)
NetCN71_2: CN71.2 U71.3(D)
NetCN72_2: CN72.2 U72.3(D)
NetCN73_2: CN73.2 U73.3(D)
NetCN74_2: CN74.2 U74.3(D)

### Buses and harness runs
bus MOTOR_D[0..3] = port MOTOR_D[0..3]

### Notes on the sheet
- Labels drawn without touching a wire or pin: MOTOR_D0, MOTOR_D1, MOTOR_D2, MOTOR_D3

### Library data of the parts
CN71-CN74 = Header 2: Header, 2-Pin
R71-R74 = Res Semi: Semiconductor Resistor

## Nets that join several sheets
3.3V: mcu (22 pins), power (C23.1 DS23.1 L1.2 U5.5), sensor (13 pins), gnss (6 pins), camera (6 pins)
3.7V_Li: power (6 pins), motor (CN71.1 CN72.1 CN73.1 CN74.1)
5V_USB: firmware (C11.1 R13.1 U2.1 U3.20), power (U4.13)
GND: mcu (19 pins), firmware (10 pins), power (18 pins), sensor (10 pins), gnss (8 pins), camera (7 pins), motor (8 pins)
DCMI_D0: mcu (U1.63), camera (U13.B4)
DCMI_D1: mcu (U1.64), camera (U13.A4)
DCMI_D2: mcu (U1.97), camera (U13.B5)
DCMI_D3: mcu (U1.98), camera (U13.A5)
DCMI_D4: mcu (U1.3), camera (U13.F5)
DCMI_D5: mcu (U1.92), camera (U13.E5)
DCMI_D6: mcu (U1.4), camera (U13.F4)
DCMI_D7: mcu (U1.5), camera (U13.E4)
MOTOR_D0: mcu (U1.59), motor (R71.2 U71.1)
MOTOR_D1: mcu (U1.60), motor (R72.2 U72.1)
MOTOR_D2: mcu (U1.61), motor (R73.2 U73.1)
MOTOR_D3: mcu (U1.62), motor (R74.2 U74.1)
NetR42_2: mcu (U1.95), sensor (R42.2 U7.23 U8.4)
NetR43_2: mcu (U1.96), sensor (R43.2 U7.24 U8.3)
NetR52_1: mcu (U1.57), gnss (R52.1 U9.4)
NetU1_25: mcu (U1.25), firmware (U3.5)
NetU1_26: mcu (U1.26), firmware (U3.1)
NetU1_51: mcu (U1.51), sensor (U7.11)
NetU1_52: mcu (U1.52), sensor (U7.12)
NetU1_55: mcu (U1.55), gnss (U9.3)
NetU1_56: mcu (U1.56), gnss (U9.2)
OV_HSYNC: mcu (U1.29), camera (U13.D2)
OV_MCO1: mcu (U1.67), camera (U13.E3)
OV_PCLK: mcu (U1.31), camera (U13.E1)
OV_PWDN: mcu (U1.30), camera (U13.B1)
OV_RESET: mcu (5 pins), camera (U13.F2)
OV_SIOC: mcu (U1.47), camera (U13.A3)
OV_SIOD: mcu (U1.48), camera (U13.A2)
OV_VSYNC: mcu (U1.93), camera (U13.D1)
